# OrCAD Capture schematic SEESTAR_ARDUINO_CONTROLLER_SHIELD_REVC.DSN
size C; title: SeeStar Arduino Shield; rev: C; note: 10021167
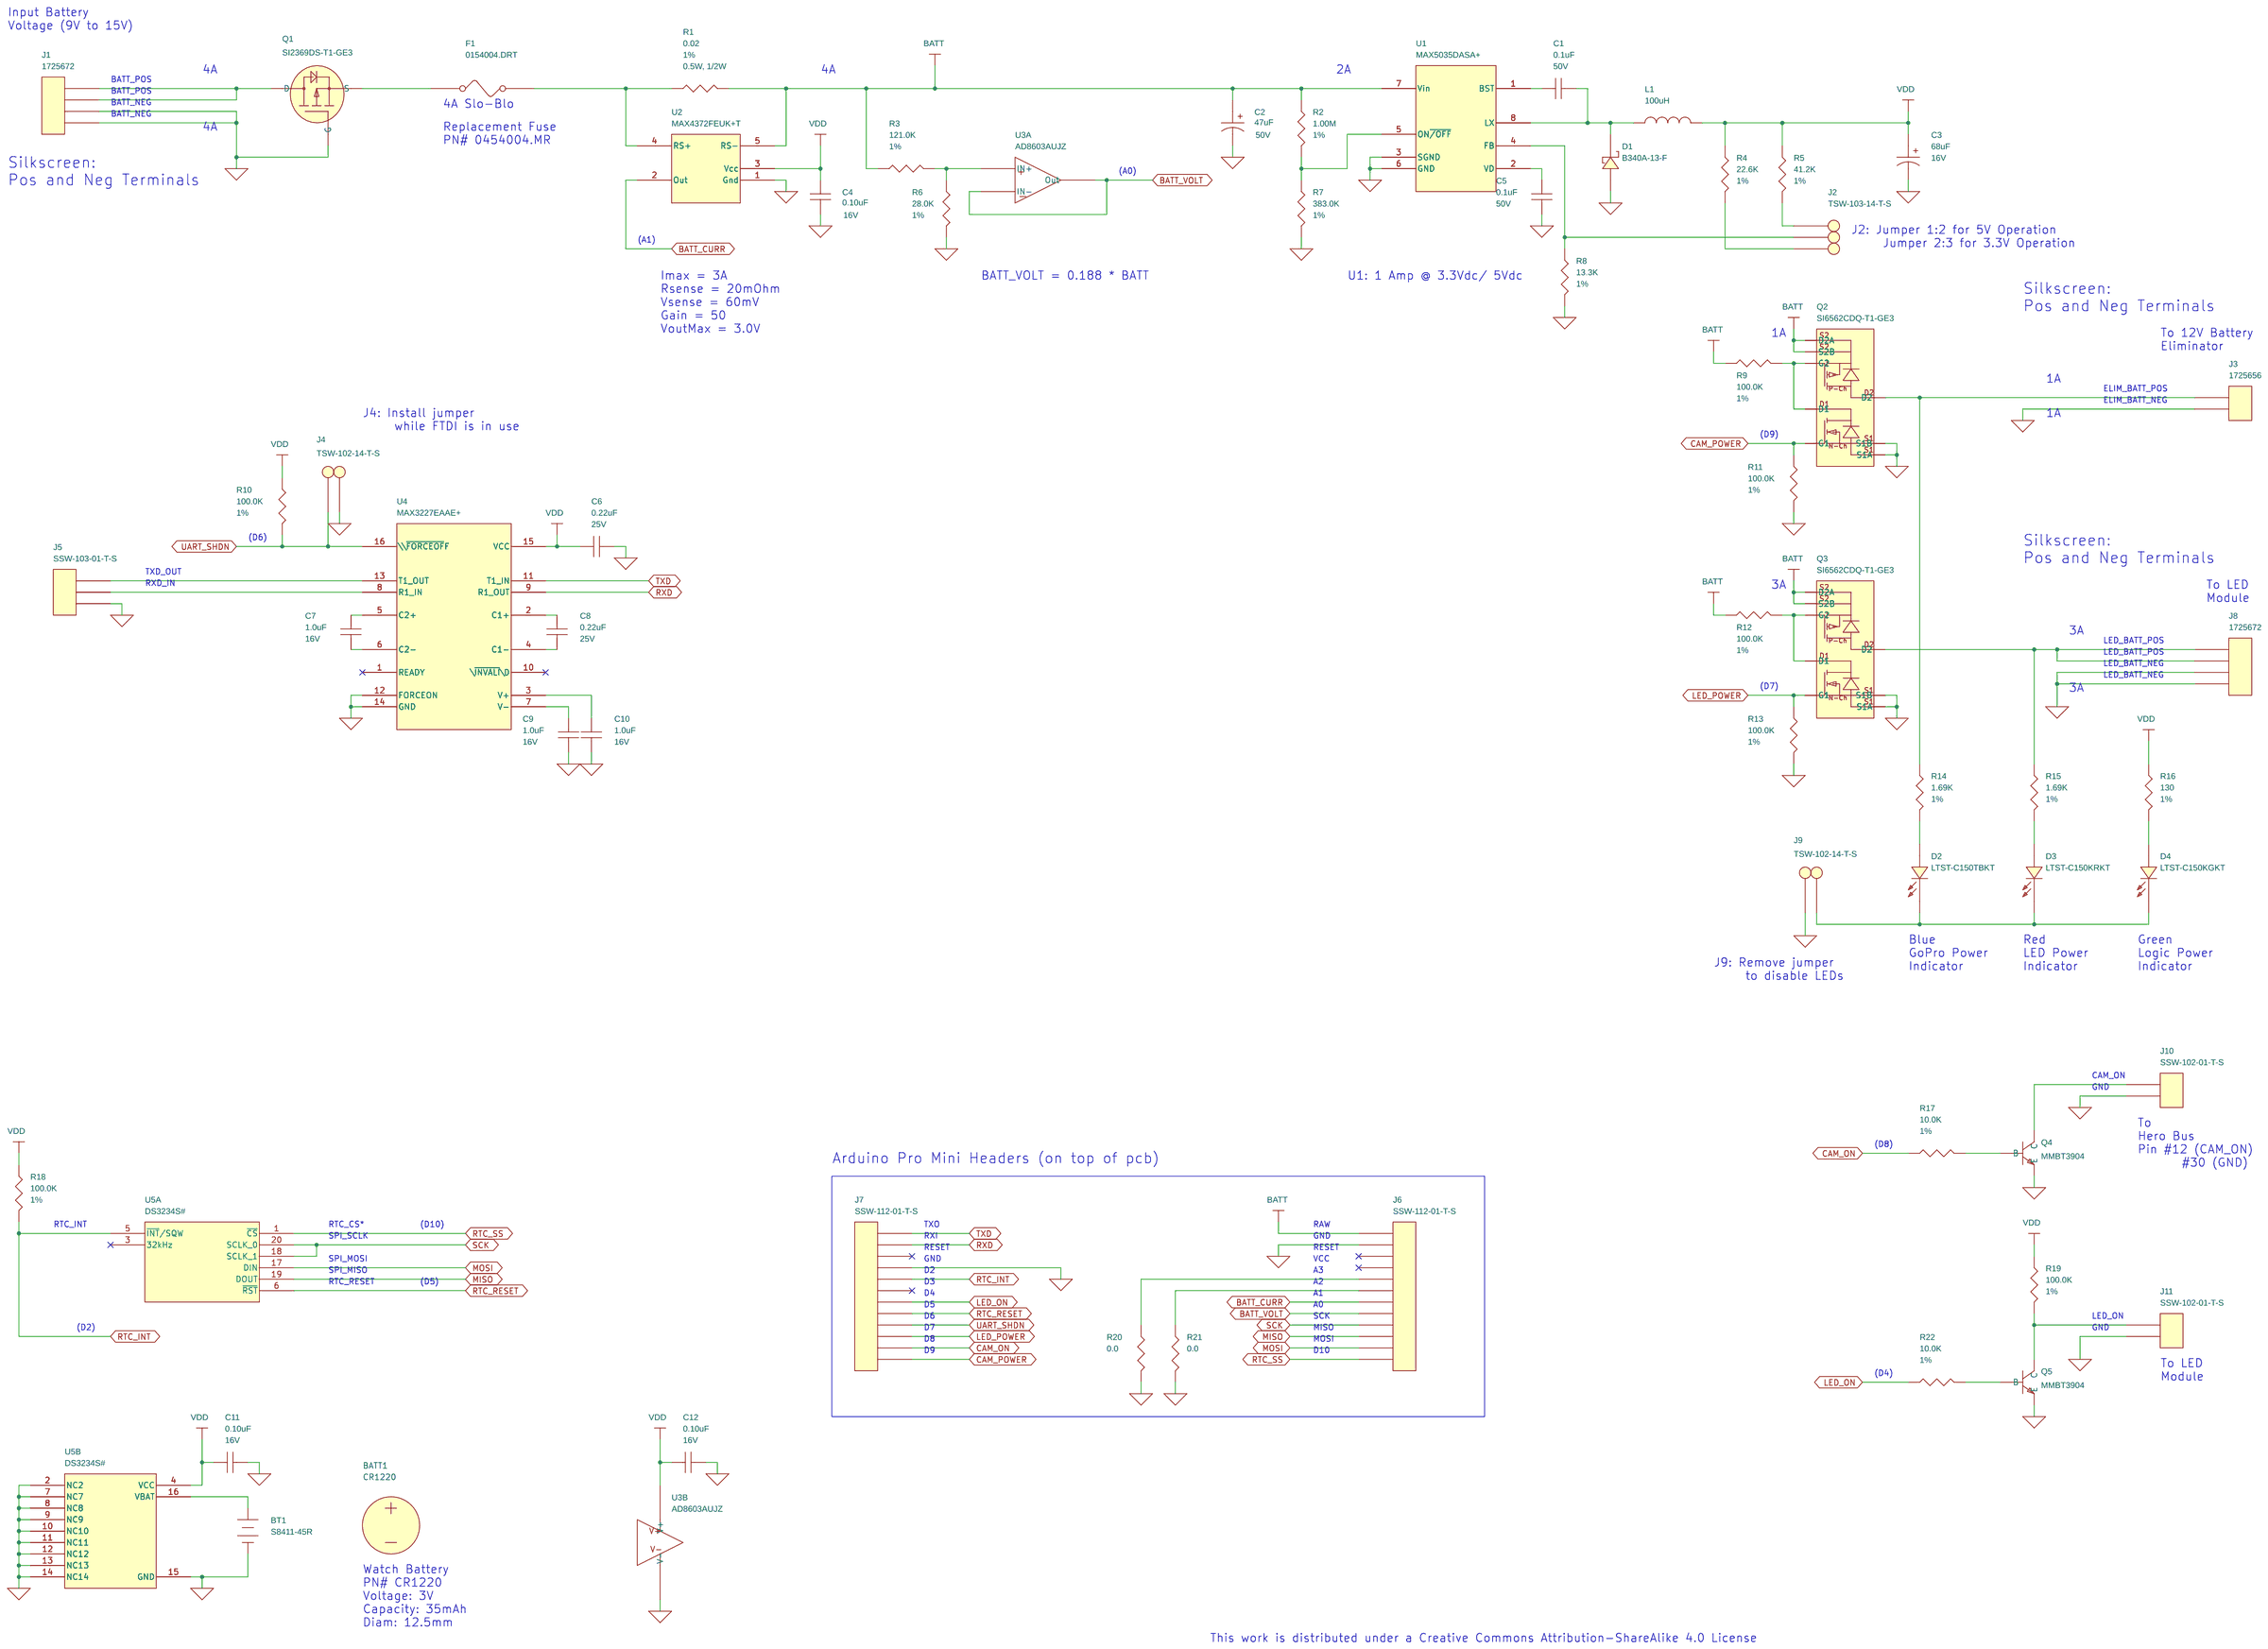
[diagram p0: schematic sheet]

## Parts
BATT1  CR1220  [UNASSIGNED]
BT1  S8411-45R  [HARWIN_S8411-45R]
C1  0.1uF  [CAPC1608X90N]
C2  47uF  [CAPAE660X800N]
C3  68uF  [CAPMP7343X310N]
C4  0.10uF  [CAPC1608X87N]
C5  0.1uF  [CAPC1608X90N]
C6  0.22uF  [CAPC1608X95N]
C7  1.0uF  [CAPC1608X90N]
C8  0.22uF  [CAPC1608X95N]
C9  1.0uF  [CAPC1608X90N]
C10  1.0uF  [CAPC1608X90N]
C11  0.10uF  [CAPC1608X87N]
C12  0.10uF  [CAPC1608X87N]
D1  B340A-13-F  [DIOM5226X230N]
D2  LTST-C150TBKT  [LED_LTST-C150xxx]
D3  LTST-C150KRKT  [LED_LTST-C150xxx]
D4  LTST-C150KGKT  [LED_LTST-C150xxx]
F1  0154004.DRT  [FUSM9750X381N]
J1  1725672  [PHOENIX_1725672]
J2  TSW-103-14-T-S  [SAMTEC_TSW-103-14]
J3  1725656  [PHOENIX_1725656]
J4  TSW-102-14-T-S  [SAMTEC_TSW-102-14]
J5  SSW-103-01-T-S  [SAMTEC_SSW-103-xx-xxx-S-x]
J6  SSW-112-01-T-S  [SAMTEC_SSW-112-xx-xxx-S-x]
J7  SSW-112-01-T-S  [SAMTEC_SSW-112-xx-xxx-S-x]
J8  1725672  [PHOENIX_1725672]
J9  TSW-102-14-T-S  [SAMTEC_TSW-102-14]
J10  SSW-102-01-T-S  [SAMTEC_SSW-102-xx-xxx-S-x]
J11  SSW-102-01-T-S  [SAMTEC_SSW-102-xx-xxx-S-x]
L1  100uH  [IND_SRN6045]
Q1  SI2369DS-T1-GE3  [SOT95P237X112-3L20N_132]
Q2  SI6562CDQ-T1-GE3  [SOP65P640X120-8L30N]
Q3  SI6562CDQ-T1-GE3  [SOP65P640X120-8L30N]
Q4  MMBT3904  [SOT95P240X130-3N_132]
Q5  MMBT3904  [SOT95P240X130-3N_132]
R1  0.02  [RESC3015X65N]
R2  1.00M  [RESC1608X50N]
R3  121.0K  [RESC1608X50N]
R4  22.6K  [RESC1608X50N]
R5  41.2K  [RESC1608X50N]
R6  28.0K  [RESC1608X50N]
R7  383.0K  [RESC1608X50N]
R8  13.3K  [RESC1608X50N]
R9  100.0K  [RESC1608X50N]
R10  100.0K  [RESC1608X50N]
R11  100.0K  [RESC1608X50N]
R12  100.0K  [RESC1608X50N]
R13  100.0K  [RESC1608X50N]
R14  1.69K  [RESC1608X50N]
R15  1.69K  [RESC1608X50N]
R16  130  [RESC1608X50N]
R17  10.0K  [RESC1608X50N]
R18  100.0K  [RESC1608X50N]
R19  100.0K  [RESC1608X50N]
R20  0.0  [RESC1608X50N]
R21  0.0  [RESC1608X50N]
R22  10.0K  [RESC1608X50N]
U1  MAX5035DASA+  [SOIC127P600X175-8N]
U2  MAX4372FEUK+T  [SOT95P280X145-5N]
U3  AD8603AUJZ  [SOT95P280X100-5N]  (sections A,B)
U4  MAX3227EAAE+  [SOP65P777X199-16L32N]
U5  DS3234S#  [SOIC127P1032X265-20N]  (sections A,B)

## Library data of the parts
BATT1 = BATT_COIN: BATTERY LITHIUM 3V COIN 12.5MM; CLASS: DISCRETE; Manufacturer: Panasonic - BSG; Package Size: 0.49" Dia x 0.08" H (12.5mm x 2.0mm)
BT1 = BATTERY: BATTERY HOLDER 12.0MM COIN SMD; CLASS: DISCRETE; Manufacturer: Harwin Inc
C1 C5 = CAP: CAP CER 0.1UF 50V 10% X7R 0603; CLASS: DISCRETE; Dielectric Type: Capacitors; Manufacturer: TDK Corporation; Manufacturer PN: C1608X7R1H104K; PART_NUMBER: C1608X7R1H104K; Package Size: 0603 (1608 Metric); Rated Voltage: 50V; TMP Manufacturer: TDK Corporation; TMP Manufacturer PN: C1608X7R1H104K; Temperature Coefficient: X7R; Tolerance: ±10%
C2 = CAP_P: CLASS: DISCRETE; Dielectric Type: Electrolytic Aluminum; Manufacturer: United Chemi-con; Manufacturer PN: EMVE500ADA470MF80G; PART_NUMBER: EMVE500ADA470MF80G; Package Size: 6.6 x 6.6 mm; Rated Voltage: 50V; Tolerance: 20%
C3 = CAP_P: CAP TANTALUM 68UF 16V 10% SMD; CLASS: DISCRETE; Dielectric Type: Tantalum; Manufacturer: AVX Corporation; Manufacturer PN: TAJD686K016RNJ; PART_NUMBER: TAJD686K016RNJ; Package Size: 2917 (7343 Metric); Rated Voltage: 16V; TMP Manufacturer: AVX Corporation; TMP Manufacturer PN: TAJD686K016RNJ; Tolerance: ±10%
C4 C11 C12 = CAP: CAP, CER, 0.10uF, 16V, 10%, X7R, 0603; CLASS: DISCRETE; Dielectric Type: Ceramic; Manufacturer: Kemet; Manufacturer PN: C0603C104K4RAC; PART_NUMBER: C0603C104K4RAC; Package Size: 0603; Rated Voltage: 16V; TMP Manufacturer: Kemet; TMP Manufacturer PN: C0603C104K4RAC; Temperature Coefficient: X7R; Tolerance: 10%
C6 C8 = CAP: CLASS: DISCRETE; Dielectric Type: Ceramic; Manufacturer: Kemet; Manufacturer PN: C0603C224K3RAC; PART_NUMBER: C0603C224K3RAC; Package Size: 0603; Rated Voltage: 25V; Temperature Coefficient: X7R; Tolerance: 10%
C7 C9 C10 = CAP: CLASS: DISCRETE; Dielectric Type: Ceramic; Manufacturer: Kemet; Manufacturer PN: C0603C105K4RAC; PART_NUMBER: C0603C105K4RAC; Package Size: 0603; Rated Voltage: 16V; Temperature Coefficient: X7R; Tolerance: 10%
D1 = DIODE_SCHOTTKY: DIODE SCHOTTKY 3A 40V SMA; CLASS: DISCRETE; Manufacturer: Diodes Inc; Package Size: DO-214AC, SMA; Rated Voltage: 500mV @ 3A
D2 = LED: LED 468NM BLUE CLEAR 1206 SMD; CLASS: DISCRETE; LED Color: Blue; Manufacturer: Lite-On Inc; Package Size: 1206 (3216 Metric); Rated Voltage: 3.3V
D3 = LED: LED SUPER RED CLEAR 1206 SMD; CLASS: DISCRETE; LED Color: Red; Manufacturer: Lite-On Inc; Package Size: 1206 (3216 Metric); Rated Voltage: 2V
D4 = LED: LED GREEN CLEAR 1206 SMD; CLASS: DISCRETE; LED Color: Green; Manufacturer: Lite-On Inc; Package Size: 1206 (3216 Metric); Rated Voltage: 2V; TMP Manufacturer: Lite-On Inc.
F1 = FUSEHOLDER_2T_2PIN: FUSE SLOW 125VAC, 125VDC 4A SMD; CLASS: DISCRETE; Manufacturer: Littelfuse Inc; Package Size: SMD w/Holder
J1 J8 = CON4: CONN TERM BLOCK 2.54MM 4POS; CLASS: IO; Contact Voltage: 125V; Manufacturer: Phoenix Contact
J2 = HEADER_3_SYM-MOD1: CONN HEADER 3POS .100" SNGL TIN; CLASS: IO; Manufacturer: Samtec Inc.; Package Size: 0.320" (8.13mm)
J3 = CON2: CONN TERM BLOCK 2.54MM 2POS; CLASS: IO; Contact Voltage: 125V; Manufacturer: Phoenix Contact
J4 J9 = HEADER_2_SYM-MOD1: CONN HEADER 2POS .100" SNGL TIN; CLASS: IO; Manufacturer: Samtec Inc.; Package Size: 0.320" (8.13mm)
J5 = CON3: CONN RCPT .100" 3POS SNGL TIN; CLASS: IO; Manufacturer: Samtec Inc; TMP Manufacturer: Samtec Inc
J6 J7 = CON12: CONN RCPT .100" 12POS SNGL TIN; CLASS: IO; Manufacturer: Samtec Inc; TMP Manufacturer: Samtec Inc
J10 J11 = CON2: CONN RCPT .100" 2POS SNGL TIN; CLASS: IO; Manufacturer: Samtec Inc; TMP Manufacturer: Samtec Inc
L1 = IND: FIXED IND 100UH 700MA 494 MOHM; CLASS: DISCRETE; Manufacturer: Bourns Inc.; Manufacturer PN: SRN6045-101M; PART_NUMBER: SRN6045-101M; Package Size: Nonstandard; Tolerance: 20%
Q1 = MOSFET_I_EP_GSD: MOSFET P-CH 30V 7.6A TO-236; CLASS: DISCRETE; Manufacturer: Vishay Siliconix; Package Size: TO-236-3, SC-59, SOT-23-3; Polarity: MOSFET P-Channel, Metal Oxide; Rated Power: 2.5W
Q2 Q3 = MOSFET_I_PN_DSSGGSSD_SYM-MOD1: MOSFET N/P-CH 20V 6.7A 8-TSSOP; CLASS: DISCRETE; Manufacturer: Vishay Siliconix; Package Size: 8-TSSOP (0.173", 4.40mm Width); Polarity: N and P-Channel; Rated Power: 1.6W, 1.7W
Q4 Q5 = BJT_NPN_BEC: TRANSISTOR GP NPN AMP SOT-23; CLASS: DISCRETE; Manufacturer: Fairchild Semiconductor; Package Size: TO-236-3, SC-59, SOT-23-3; Polarity: NPN; Rated Power: 350mW
R1 = RES: RES SMD 0.02 OHM 1% 1/2W 1206; CLASS: DISCRETE; Manufacturer: Stackpole Electronics Inc; Manufacturer PN: CSR1206FK20L0; PART_NUMBER: CSR1206FK20L0; Package Size: 1206 (3216 Metric); Rated Power: 0.5W, 1/2W; Tolerance: 1%
R2 = RES: CLASS: DISCRETE; Manufacturer: Vishay; Manufacturer PN: CRCW06031M00FKEA; PART_NUMBER: CRCW06031M00FKEA; Package Size: 0603; Rated Power: 0.1W; TMP Manufacturer: Vishay; TMP Manufacturer PN: CRCW06031M00FKEA; Temperature Coefficient: 100ppm/K; Tolerance: 1%
R3 = RES: CLASS: DISCRETE; Manufacturer: Vishay; Manufacturer PN: CRCW0603121KFKEA; PART_NUMBER: CRCW0603121KFKEA; Package Size: 0603; Rated Power: 0.1W; TMP Manufacturer: Vishay; TMP Manufacturer PN: CRCW0603121KFKEA; Temperature Coefficient: 100ppm/K; Tolerance: 1%
R4 = RES: CLASS: DISCRETE; Manufacturer: Vishay; Manufacturer PN: CRCW060322K6FKEA; PART_NUMBER: CRCW060322K6FKEA; Package Size: 0603; Rated Power: 0.1W; Temperature Coefficient: 100ppm/K; Tolerance: 1%
R5 = RES: CLASS: DISCRETE; Manufacturer: Vishay; Manufacturer PN: CRCW060341K2FKEA; PART_NUMBER: CRCW060341K2FKEA; Package Size: 0603; Rated Power: 0.1W; Temperature Coefficient: 100ppm/K; Tolerance: 1%
R6 = RES: CLASS: DISCRETE; Manufacturer: Vishay; Manufacturer PN: CRCW060328K0FKEA; PART_NUMBER: CRCW060328K0FKEA; Package Size: 0603; Rated Power: 0.1W; Temperature Coefficient: 100ppm/K; Tolerance: 1%
R7 = RES: CLASS: DISCRETE; Manufacturer: Vishay; Manufacturer PN: CRCW0603383KFKEA; PART_NUMBER: CRCW0603383KFKEA; Package Size: 0603; Rated Power: 0.1W; TMP Manufacturer: Vishay; TMP Manufacturer PN: CRCW0603383KFKEA; Temperature Coefficient: 100ppm/K; Tolerance: 1%
R8 = RES: CLASS: DISCRETE; Manufacturer: Vishay; Manufacturer PN: CRCW060313K3FKEA; PART_NUMBER: CRCW060313K3FKEA; Package Size: 0603; Rated Power: 0.1W; Temperature Coefficient: 100ppm/K; Tolerance: 1%
R9-R13 R18 R19 = RES: RES 100K OHM 1/10W 1% 0603 SMD; CLASS: DISCRETE; Manufacturer: Vishay/Dale; Manufacturer PN: CRCW0603100KFKEA; PART_NUMBER: CRCW0603100KFKEA; Package Size: 0603; Rated Power: 0.1W; TMP Manufacturer: Vishay; TMP Manufacturer PN: CRCW0603100KFKEA; Temperature Coefficient: 100ppm/K; Tolerance: 1%
R14 R15 = RES: CLASS: DISCRETE; Manufacturer: Vishay; Manufacturer PN: CRCW06031K69FKEA; PART_NUMBER: CRCW06031K69FKEA; Package Size: 0603; Rated Power: 0.1W; Temperature Coefficient: 100ppm/K; Tolerance: 1%
R16 = RES: CLASS: DISCRETE; Manufacturer: Vishay; Manufacturer PN: CRCW0603130RFKEA; PART_NUMBER: CRCW0603130RFKEA; Package Size: 0603; Rated Power: 0.1W; Temperature Coefficient: 100ppm/K; Tolerance: 1%
R17 R22 = RES: CLASS: DISCRETE; Manufacturer: Vishay; Manufacturer PN: CRCW060310K0FKEA; PART_NUMBER: CRCW060310K0FKEA; Package Size: 0603; Rated Power: 0.1W; TMP Manufacturer: Vishay; TMP Manufacturer PN: CRCW060310K0FKEA; Temperature Coefficient: 100ppm/K; Tolerance: 1%
R20 R21 = RES: RES 0.0 OHM 1/10W 0603 SMD; CLASS: DISCRETE; Manufacturer: Vishay/Dale; Manufacturer PN: CRCW06030000Z0EA; PART_NUMBER: CRCW06030000Z0EA; Package Size: 0603 (1608 Metric); Rated Power: 0.1W, 1/10W; TMP Manufacturer: Vishay/Dale; TMP Manufacturer PN: CRCW06030000Z0EA; Tolerance: Jumper
U1 = MAX5035: IC REG BUCK ADJ 1A 8SOIC; CLASS: IC; Manufacturer: Maxim Integrated; Package Size: 8-SOIC (0.154", 3.90mm Width)
U2 = MAX4372xEUK-T_SYM-MOD1: IC AMP GAIN +50V/V PREC SOT23-5; CLASS: IC; Manufacturer: Maxim Integrated Products; PART_NUMBER: MAX4372FEUK+T_SYM-MOD1; Package Size: SOT-23-5, SC-74A, SOT-25; Supply Voltage: 2.7 V ~ 28 V
U3 = AD8603: IC OPAMP GP R-R CMOS TSOT23-5; CLASS: IC; Manufacturer: Analog Devices Inc; Manufacturer PN: AD8603AUJZ-REEL7; PART_NUMBER: AD8603AUJZ-REEL7; POWER_GROUP: 1; Package Size: SOT-23-5 Thin, TSOT-23-5; Supply Voltage: 1.8 V ~ 5 V, ±0.9 V ~ 2.5 V; TMP Manufacturer: Analog Devices; TMP Manufacturer PN: AD8603AUJZ-REEL7
U4 = MAX3227E: IC TXRX RS-232 W/SHTDWN 16-SSOP; CLASS: IC; Manufacturer: Maxim Integrated; Package Size: 16-SSOP (0.209", 5.30mm Width); Supply Voltage: 3 V - 5.5 V
U5 = DS3234Sx: IC RTC W/TCXO 20-SOIC; CLASS: IC; Manufacturer: Maxim Integrated Products; POWER_GROUP: 2; Package Size: 20-SOIC (0.295", 7.50mm Width); Supply Voltage: 2 V ~ 5.5 V; TMP Manufacturer: Maxim Integrated Products

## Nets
GND_SIGNAL: BT1.2(-) C2.2 C3.2 C4.2 C5.2 C6.2 C9.2 C10.2 C11.2 C12.2 D1.A J1.3 J1.4 J3.2 J4.2 J5.3 J6.2 J7.9 J8.3 J8.4 J9.1 J10.2 J11.2 Q1.1(G) Q2.2(S1B) Q2.3(S1A) Q3.2(S1B) Q3.3(S1A) Q4.2(E) Q5.2(E) R6.2 R7.2 R8.2 R11.2 R13.2 R20.2 R21.2 U1.3(SGND) U1.6(GND) U2.1(Gnd) U3.2(V-) U4.12(FORCEON) U4.14(GND) U5.2(NC2) U5.7(NC7) U5.8(NC8) U5.9(NC9) U5.10(NC10) U5.11(NC11) U5.12(NC12) U5.13(NC13) U5.14(NC14) U5.15(GND)
VDD: C3.1 C4.1 C6.1 C11.1 C12.1 L1.2 R4.1 R5.1 R10.1 R16.1 R18.1 R19.1 U2.3(Vcc) U3.5(V+) U4.15(VCC) U5.4(VCC)
BATT: C2.1 J6.1 Q2.6(S2B) Q2.7(D2A) Q3.6(S2B) Q3.7(D2A) R1.2 R2.1 R3.1 R9.2 R12.2 U1.7(Vin) U2.5(RS-)
BATT_CURR: J6.7 U2.2(Out)
BATT_VOLT: J6.8 U3.1(Out) U3.4(IN-)
CAM_ON: J7.2 R17.1
CAM_POWER: J7.1 Q2.4(G1) R11.1
LED_ON: J7.6 R22.1
LED_POWER: J7.3 Q3.4(G1) R13.1
MISO: J6.10 U5.19(DOUT)
MOSI: J6.11 U5.17(DIN)
RTC_INT: J7.8 R18.2 U5.5(~{INT}/SQW)
RTC_RESET: J7.5 U5.6(~{RST})
RTC_SS: J6.12 U5.1(~{CS})
RXD: J7.11 U4.9(R1_OUT)
SCK: J6.9 U5.18(SCLK_1) U5.20(SCLK_0)
TXD: J7.12 U4.11(T1_IN)
UART_SHDN: J4.1 J7.4 R10.2 U4.16(\\~{FORCEOF}F)
N15180757: J11.1 Q5.3(C) R19.2
N15180795: Q5.1(B) R22.2
N15180973: J1.1 J1.2 Q1.3(D)
N15180993: J8.1 J8.2 Q3.8(D2) R15.1
N15181069: J6.6 R21.1
N15181133: J6.5 R20.1
N15181323: F1.1 Q1.2(S)
N15181327: F1.2 R1.1 U2.4(RS+)
N15181383: D4.A R16.2
N15181515: R3.2 R6.1 U3.3(IN+)
N15181811: J10.1 Q4.3(C)
N15181975: BT1.1(+) U5.16(VBAT)
N15182163: Q4.1(B) R17.2
N15182191: J5.1 U4.13(T1_OUT)
N15182195: J5.2 U4.8(R1_IN)
N15182295: D2.A R14.2
N15182299: D3.A R15.2
N15182387: J3.1 Q2.8(D2) R14.1
N15182531: D2.C D3.C D4.C J9.2
N15183153: R2.2 R7.1 U1.5(ON~{/OFF})
N15183237: C1.2 D1.C L1.1 U1.8(LX)
N15183261: J2.2 R8.1 U1.4(FB)
N15183297: C5.1 U1.2(VD)
N15183305: C1.1 U1.1(BST)
N15187989: Q3.1(D1) Q3.5(G2) R12.1
N15190814: Q2.1(D1) Q2.5(G2) R9.1
N15195894: J2.3 R4.2
N15201520: C7.2 U4.6(C2-)
N15201524: C7.1 U4.5(C2+)
N15201528: C8.2 U4.4(C1-)
N15201532: C8.1 U4.2(C1+)
N15201790: C9.1 U4.7(V-)
N15201913: C10.1 U4.3(V+)
N15224170: J2.1 R5.2

Not connected (* = marked no-connect by the designer): J6 3* 4*; J7 7* 10*; U4 1(READY)* 10(\~{INVALI}\D)*; U5 3(32kHz)*

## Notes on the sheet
- Input Battery
  Voltage (9V to 15V)
- 4A
- 4A
- 2A
- BATT_POS
- BATT_POS
- BATT_NEG
- 4A Slo-Blo
- BATT_NEG
- 4A
- Replacement Fuse
  PN# 0454004.MR
- Silkscreen:
  Pos and Neg Terminals
- (A0)
- J2: Jumper 1:2 for 5V Operation
       Jumper 2:3 for 3.3V Operation
- (A1)
- Imax = 3A
  Rsense = 20mOhm
  Vsense = 60mV
  Gain = 50
  VoutMax = 3.0V
- BATT_VOLT = 0.188 * BATT
- U1: 1 Amp @ 3.3Vdc/ 5Vdc
- Silkscreen:
  Pos and Neg Terminals
- 1A
- To 12V Battery
  Eliminator
- 1A
- ELIM_BATT_POS
- ELIM_BATT_NEG
- J4: Install jumper
       while FTDI is in use
- 1A
- (D9)
- (D6)
- Silkscreen:
  Pos and Neg Terminals
- RXD_IN
- TXD_OUT
- 3A
- To LED
  Module
- 3A
- LED_BATT_POS
- LED_BATT_POS
- LED_BATT_NEG
- LED_BATT_NEG
- (D7)
- 3A
- Blue
  GoPro Power
  Indicator
- Red
  LED Power
  Indicator
- Green
  Logic Power
  Indicator
- J9: Remove jumper
       to disable LEDs
- CAM_ON
- GND
- To
  Hero Bus
  Pin #12 (CAM_ON)
         #30 (GND)
- (D8)
- Arduino Pro Mini Headers (on top of pcb)
- RTC_INT
- RTC_CS*
- (D10)
- TXO
- RAW
- SPI_SCLK
- RXI
- GND
- SPI_MOSI
- GND
- RESET
- RESET
- VCC
- SPI_MISO
- D2
- A3
- RTC_RESET
- (D5)
- D3
- A2
- D4
- A1
- D5
- A0
- (D2)
- D6
- D7
- MISO
- SCK
- GND
- LED_ON
- D8
- MOSI
- D9
- D10
- To LED
  Module
- (D4)
- Watch Battery
  PN# CR1220
  Voltage: 3V
  Capacity: 35mAh
  Diam: 12.5mm
- This work is distributed under a Creative Commons Attribution-ShareAlike 4.0 License
